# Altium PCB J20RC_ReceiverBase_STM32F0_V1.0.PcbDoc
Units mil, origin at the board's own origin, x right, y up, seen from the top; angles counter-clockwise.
Board outline 1700 x 955 mil, 2 copper layers (Top Layer, Bottom Layer); 27 components, 0 nets, 129 pads, 46 vias.
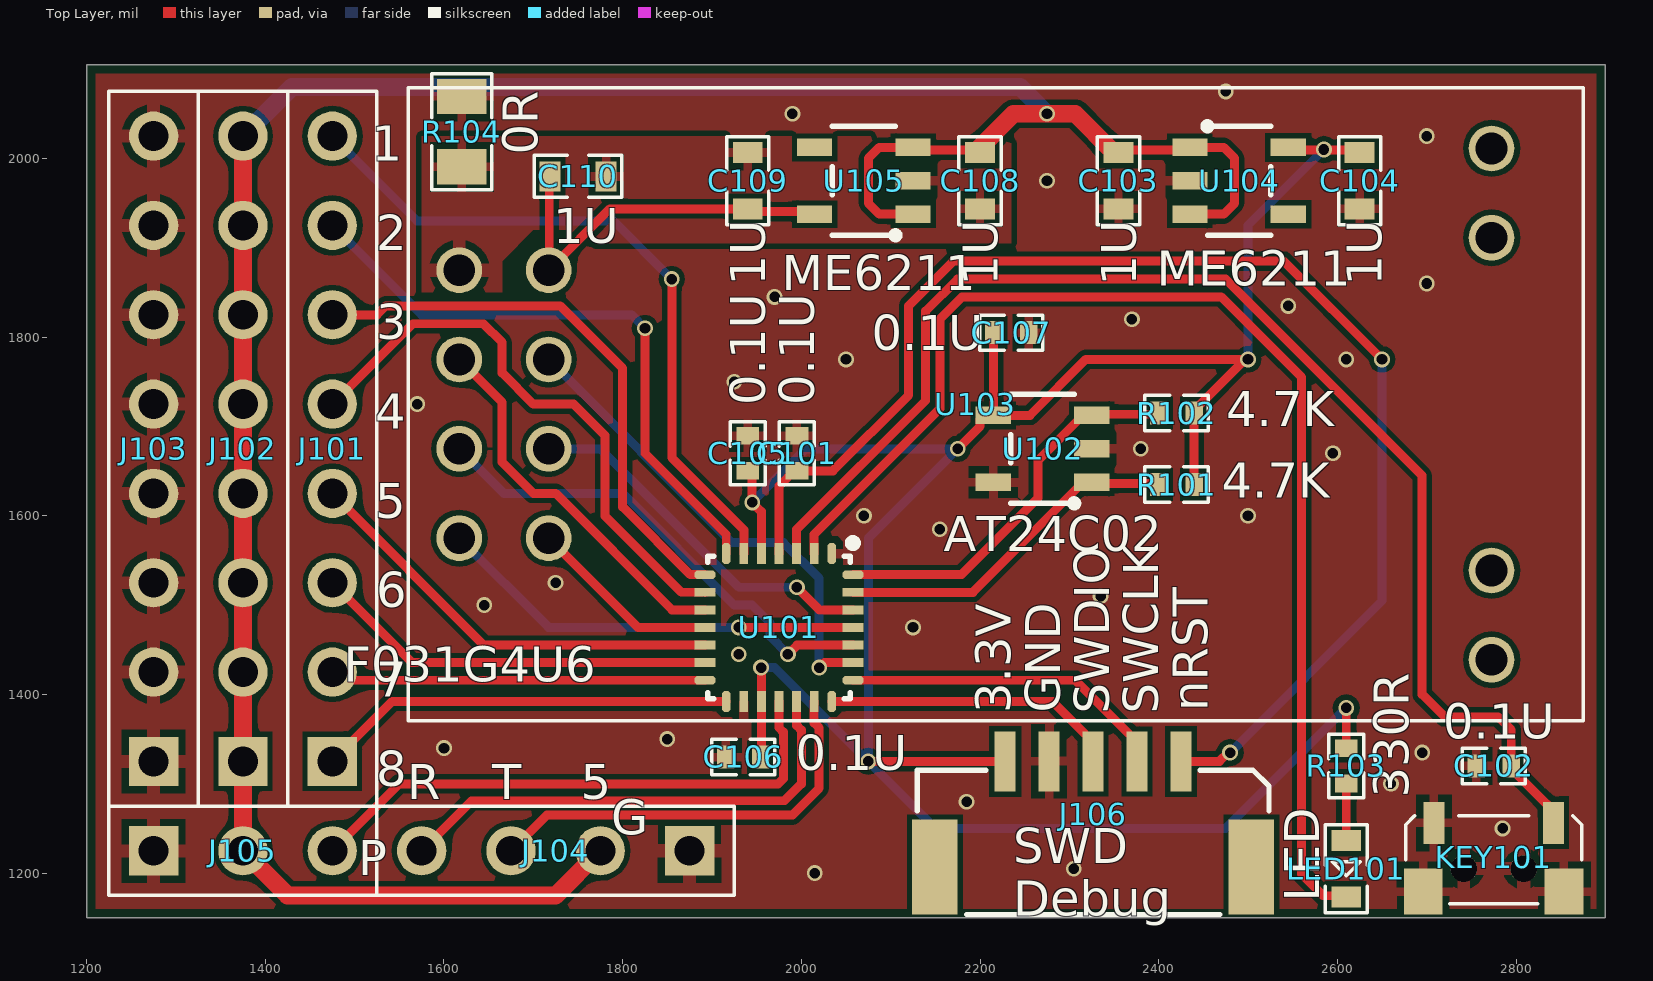
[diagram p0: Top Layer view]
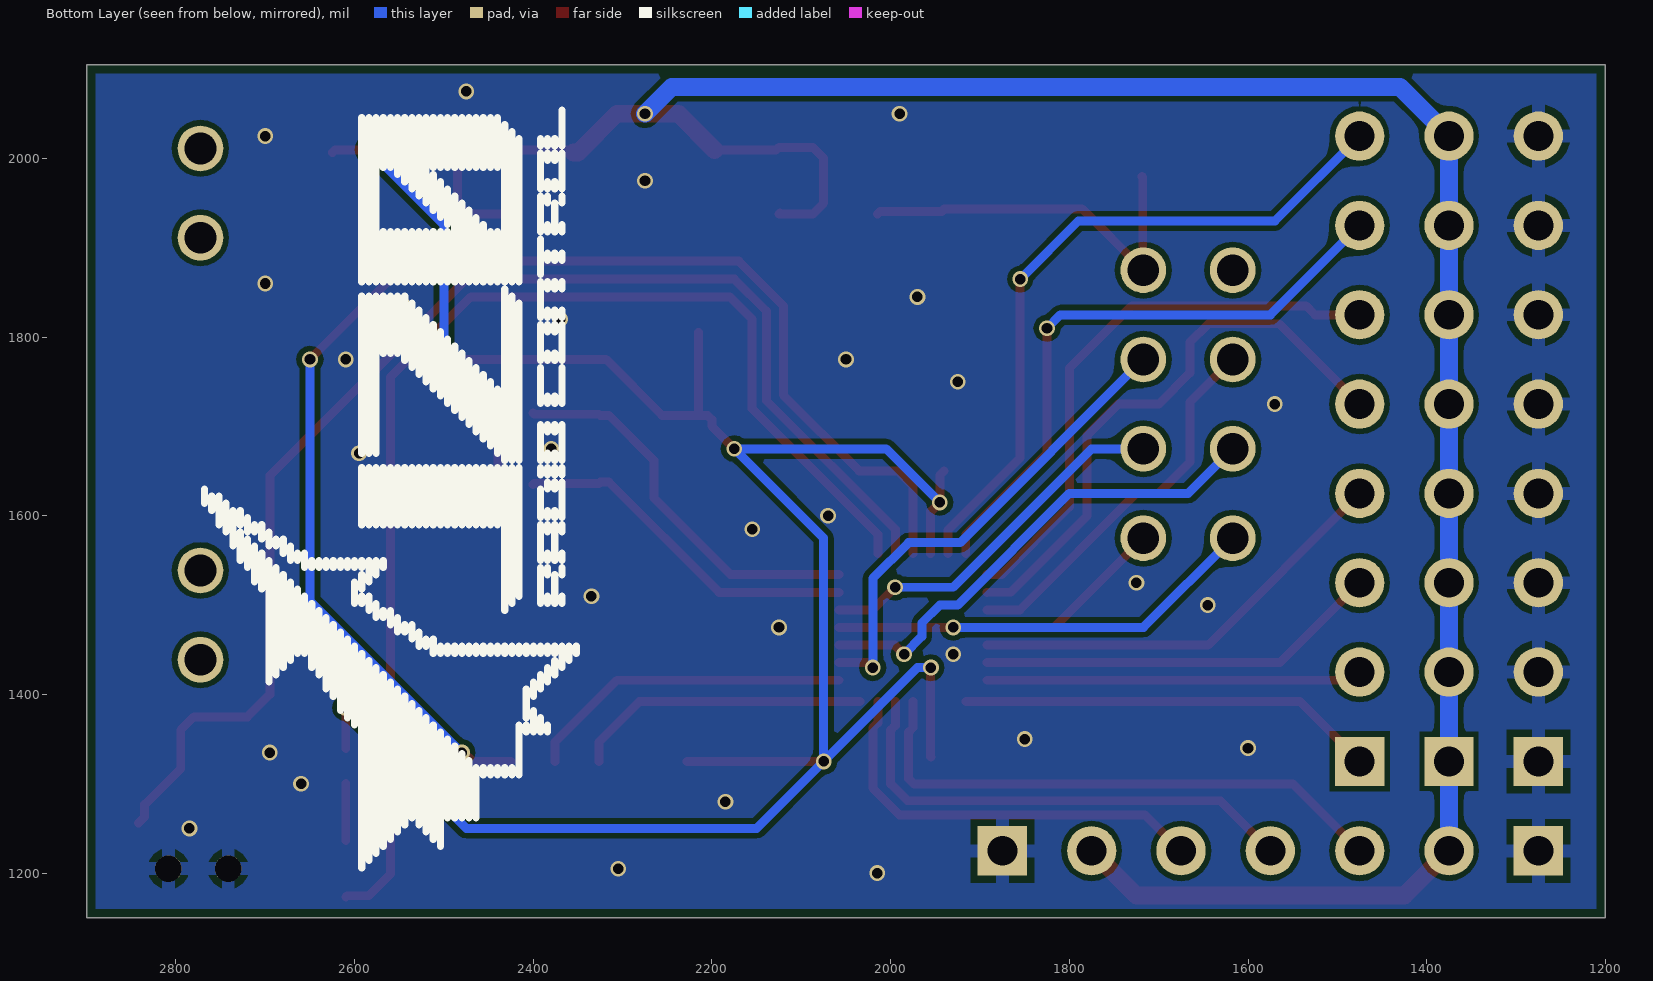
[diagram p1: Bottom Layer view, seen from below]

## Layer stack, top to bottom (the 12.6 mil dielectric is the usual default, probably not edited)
Top Solder: solder mask 0.4, Solder Resist, Dk 3.5
Top Layer: signal copper 1.4
Dielectric 1: dielectric 12.6, FR-4, Dk 4.8
Bottom Layer: signal copper 1.4
Bottom Solder: solder mask 0.4, Solder Resist, Dk 3.5

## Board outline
1200,1150 1200,2105 2900,2105 2900,1150

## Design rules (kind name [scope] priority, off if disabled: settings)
Clearance [All] p1: gap=10 ignorepadtopadclearanceinfootprint=FALSE except(0: Arc-Hole Track-Hole SMDPad-Hole THPad-Hole Via-Hole Fill-Hole Poly-Hole Region-Hole Text-Hole)
PolygonConnect [All] p1: connectstyle=Relief reliefconductorwidth=10 reliefentries=4 polygonreliefangle="90 Angle" airgapwidth=10
RoutingVias [All] p1: holewidth=28 width=50 viastyle="Through Hole" minholewidth=28 minwidth=50 maxholewidth=28 maxwidth=50
SolderMaskExpansion [All] p1: expansion=4
Width [All] p1: maxlimit=10 minlimit=10 preferedwidth=10
30 further rules are at their usual default settings.

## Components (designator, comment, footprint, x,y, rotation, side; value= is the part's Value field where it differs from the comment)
C101 "CAP" 0402 1995,1670 r90 top
C102 "CAP" 0402 2775,1320 r0 top
C103 "CAP" 0603 2355,1975 r90 top
C104 "CAP" 0603 2625,1975 r90 top
C105 "CAP" 0402 1940,1670 r270 top
C106 "CAP" 0402 1935,1330 r0 top
C107 "CAP" 0402 2235,1805 r180 top
C108 "CAP" 0603 2200,1975 r90 top
C109 "CAP" 0603 1940,1975 r270 top
C110 "CAP" 0603 1750,1980 r180 top
J101 "Header_8" Header_8_2.54 1475,1675 r90 top
J102 "Header_8" Header_8_2.54 1375,1675 r90 top
J103 "Header_8" Header_8_2.54 1275,1675 r90 top
J104 "Header_4" Header_4_2.54 1725,1225 r180 top
J105 "Header_3" Header_3_2.54 1375,1225 r0 top
J106 "IO5" GH1.25-5P 2425,1325 r270 top
KEY101 "KEY_2*4" KEY_2*4 2775,1205 r180 top
LED101 "LED" 0603_LED 2610,1205 r270 top
R101 "RES" 0402 2420,1635 r180 top
R102 "RES" 0402 2420,1715 r180 top
R103 "RES" 0402 2610,1320 r270 top
R104 "RES" 0805 1620,2030 r90 top
U101 "STM32F031G4U6" UFQFPN-28 1975,1475 r180 top
U102 "AT24C02D" SOT-23-5 2270,1675 r0 top
U103 "E01_2G4M27D" E01_2G4M27D 2875,1725 r90 top locked
U104 "ME6211" SOT-23-5 2490,1975 r180 top
U105 "ME6211" SOT-23-5 2070,1975 r0 top

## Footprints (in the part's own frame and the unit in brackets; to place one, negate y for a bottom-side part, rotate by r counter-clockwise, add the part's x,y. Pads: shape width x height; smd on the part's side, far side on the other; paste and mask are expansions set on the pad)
0402 [mm]
  rect 0.5x0.65 smd: 1(-0.5,0) 2(0.5,0)
  silkscreen extent -0.9,-0.5 0.9,0.5
0603 [mm]
  rect 0.6x0.85 smd: 1(-0.8,0) 2(0.8,0)
  silkscreen extent -1.25,-0.6 1.25,0.6
0603_LED [mm]
  rect 0.6x0.85 smd: 1(-0.8,0) 2(0.8,0)
  silkscreen extent -1.25,-0.6 1.25,0.6
0805 [mm]
  rect 1x1.4 smd: 1(-1,0) 2(1,0)
  silkscreen extent -1.65,-0.85 1.65,0.85
E01_2G4M27D [mm]
  round 1.3 hole 0.9: 1(3.81,31.95) 2(3.81,29.41) 3(1.27,31.95) 4(1.27,29.41) 5(-1.27,31.95) 6(-1.27,29.41) 7(-3.81,31.95) 8(-3.81,29.41) 9(7.27,2.6) 10(4.73,2.6) 11(-4.73,2.6) 12(-7.27,2.6)
  silkscreen extent -9,0 9,33.4
GH1.25-5P [mm]
  rect 1.7x0.6 smd: 1(0,0) 2(0,-1.25) 3(0,-2.5) 4(0,-3.75) 5(0,-5)
  rect 2.7x1.3 smd: 6(3,2) 7(3,-7)
  silkscreen extent 0.25,-7.5 4.35,2.5
Header_3_2.54 [mm]
  rect 1.4x1.4 hole 0.85: 1(-2.54,0)
  round 1.4 hole 0.85: 2(0,0) 3(2.54,0)
  silkscreen extent -3.81,-1.27 3.81,1.27
Header_4_2.54 [mm]
  rect 1.4x1.4 hole 0.85: 1(-3.81,0)
  round 1.4 hole 0.85: 2(-1.27,0) 3(1.27,0) 4(3.81,0)
  silkscreen extent -5.08,-1.27 5.08,1.27
Header_8_2.54 [mm]
  rect 1.4x1.4 hole 0.85: 1(-8.89,0)
  round 1.4 hole 0.85: 2(-6.35,0) 3(-3.81,0) 4(-1.27,0) 5(1.27,0) 6(3.81,0) 7(6.35,0) 8(8.89,0)
  silkscreen extent -10.16,-1.27 10.16,1.27
KEY_2*4 [mm]
  rect 0.6x1.2 smd: 1(-1.7,-1.3) 2(1.7,-1.3)
  rect 1.1x1.3 smd: 3(-2,0.65) 4(2,0.65)
  round 0.75 hole 0.75: 5(-0.85,0) 6(0.85,0)
  silkscreen extent -2.5,-1.5 2.5,1
SOT-23-5 [mm]
  rect 1x0.5 smd: 1(1.4,-0.95) 2(1.4,0) 3(1.4,0.95) 4(-1.4,0.95) 5(-1.4,-0.95)
  silkscreen extent -0.9,-1.68 1.03,1.55
UFQFPN-28 [mm]
  oct 0.25x0.6 smd: 1(-1.5,-2.1) 7(1.5,-2.1) 15(1.5,2.1) 21(-1.5,2.1)
  rect 0.25x0.6 smd: 2(-1,-2.1) 3(-0.5,-2.1) 4(0,-2.1) 5(0.5,-2.1) 6(1,-2.1) 16(1,2.1) 17(0.5,2.1) 18(0,2.1) 19(-0.5,2.1) 20(-1,2.1)
  oct 0.6x0.25 smd: 8(2.1,-1.5) 14(2.1,1.5) 22(-2.1,1.5) 28(-2.1,-1.5)
  rect 0.6x0.25 smd: 9(2.1,-1) 10(2.1,-0.5) 11(2.1,0) 12(2.1,0.5) 13(2.1,1) 23(-2.1,1) 24(-2.1,0.5) 25(-2.1,0) 26(-2.1,-0.5) 27(-2.1,-1)
  silkscreen extent -2.2,-2.5 2.02,2.02

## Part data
C101 C102 C103 C104 C105 C106 C107 C108 C109 C110: "无极性电容"
J101 J102 J103: "8P_排针"
J104: "4P_排针"
J105: "3P_排针"
R101 R102 R103 R104: "电阻"
U101: library part QFN28_ALL, "STM32F***G*U6"
U104 U105: "500mA LDO"

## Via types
v1: diameter 17.72, hole 11.81, Top Layer to Bottom Layer, tented both sides, 46 vias

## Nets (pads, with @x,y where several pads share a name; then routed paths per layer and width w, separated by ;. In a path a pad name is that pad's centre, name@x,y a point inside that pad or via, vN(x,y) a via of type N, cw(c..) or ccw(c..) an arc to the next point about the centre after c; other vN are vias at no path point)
pads on no net: C101.1 C101.2 C102.1 C102.2 C103.1 C103.2 C104.1 C104.2 C105.1 C105.2 C106.1 C106.2 C107.1 C107.2 C108.1 C108.2 C109.1 C109.2 C110.1 C110.2 J101.1 J101.2 J101.3 J101.4 J101.5 J101.6 J101.7 J101.8 J102.1 J102.2 J102.3 J102.4 J102.5 J102.6 J102.7 J102.8 J103.1 J103.2 J103.3 J103.4 J103.5 J103.6 J103.7 J103.8 J104.1 J104.2 J104.3 J104.4 J105.1 J105.2 J105.3 J106.1 J106.2 J106.3 J106.4 J106.5 J106.6 J106.7 KEY101.1 KEY101.2 KEY101.3 KEY101.4 KEY101.5 KEY101.6 LED101.1 LED101.2 R101.1 R101.2 R102.1 R102.2 R103.1 R103.2 R104.1 R104.2 U101.1 U101.2 U101.3 U101.4 U101.5 U101.6 U101.7 U101.8 U101.9 U101.10 U101.11 U101.12 U101.13 U101.14 U101.15 U101.16 U101.17 U101.18 U101.19 U101.20 U101.21 U101.22 U101.23 U101.24 U101.25 U101.26 U101.27 U101.28 U102.1 U102.2 U102.3 U102.4 U102.5 U103.1 U103.2 U103.3 U103.4 U103.5 U103.6 U103.7 U103.8 U103.9 U103.10 U103.11 U103.12 U104.1 U104.2 U104.3 U104.4 U104.5 U105.1 U105.2 U105.3 U105.4 U105.5
copper on no net: | length 21773
  Top Layer w10: 1475,1225 1550,1300 1974.14,1300 1980,1305.86 1980,1357.8 1975,1362.8 1975,1392.32 ; 1475,1325 1542.32,1392.32 1915.94,1392.32 ; 1475,1425 1487.21,1425 1496.26,1415.94 1892.32,1415.94 ; 1475,1525 1564.37,1435.63 1892.32,1435.63 ; 1475,1625 1644.69,1455.31 1892.32,1455.31 ; 1475,1725 1565,1815 1644.14,1815 1665,1794.14 1665,1760 1700,1725 1745,1725 1780,1690 1780,1600 1865.55,1514.45 1892.24,1514.45 1892.32,1514.37 ; 1475,1825 1525,1825 1535,1835 1730,1835 1800,1765 1800,1610 1875.87,1534.13 1892.24,1534.13 1892.32,1534.06 ; 1575,1225 1631,1281 1981,1281 2000,1300 2000,1360 1994.68,1365.32 1994.68,1392.32 ; 1617.13,1775 1665,1727.13 1665,1660 1700,1625 1725,1625 1855.24,1494.76 1892.24,1494.76 1892.32,1494.68 ; 1675,1225 1715,1265 1990,1265 2020,1295 2020,1362.63 2014.37,1368.26 2014.37,1392.32 ; 1717.13,1575 1817.13,1475 1892.32,1475 ; 1717.13,1875 1717.81,1875.69 ; 1718.5,1980 1717.81,1979.31 1717.81,1875.69 ; v1(1825,1810) 1825,1670 1915.94,1579.06 1915.94,1557.68 ; v1(1855,1865) 1855,1665 1935.63,1584.37 1935.63,1557.68 ; v1(1930,1475) 2057.68,1475 ; 1940,1650.32 1940.16,1650.32 1945,1645.48 v1(1945,1615) 1955.32,1604.68 1955.32,1557.68 ; 1954.68,1330 1955.23,1330.55 1955.23,1392.24 1955.31,1392.32 1955.23,1392.4 1955.23,1429.77 v1(1955,1430) ; 1975,1557.68 1975,1633.26 1992.05,1650.32 1995,1650.32 2035.32,1650.32 2120,1735 2120,1835 2170,1885 2540,1885 v1(2650,1775) ; v1(1985,1445) 1995.32,1455.32 2057.68,1455.32 ; 1994.68,1557.68 1994.68,1584.68 2139,1729 2139,1829 2175,1865 2475,1865 2695,1645 2695,1400 2720,1375 2780,1375 2794.68,1360.32 2794.68,1320 2794.68,1317.04 2835.12,1276.61 2835.12,1262.99 2841.93,1256.18 ; v1(1995,1520) 2020.32,1494.68 2057.68,1494.68 ; 2014.37,1557.68 2014.37,1579.37 2155,1720 2155,1820 2180,1845 2470,1845 2560,1755 2560,1198.84 2584.13,1174.71 2608.79,1174.71 2610,1173.5 ; 2014.88,1937.6 2011.93,1940.55 1942.95,1940.55 1940,1943.5 1785.63,1943.5 1717.81,1875.69 ; v1(2020,1430) 2025.63,1435.63 2057.68,1435.63 ; 2034.06,1392.32 2280.93,1392.32 2326.58,1346.67 2326.58,1325 ; 2057.68,1415.94 2306.51,1415.94 2375.78,1346.68 2375.78,1325.01 ; 2057.68,1514.37 2192.05,1514.37 2315.28,1637.6 2325.12,1637.6 2326.42,1636.3 2399.02,1636.3 2400.31,1635 ; 2057.68,1534.06 2179.06,1534.06 2265,1620 2265,1662.13 2315.28,1712.4 2325.12,1712.4 2326.42,1713.7 2399.02,1713.7 2400.32,1715 ; v1(2075,1325) 2228.15,1325.01 ; 2124.01,1938.71 2125.12,1937.6 2087.4,1937.6 2075,1950 2075,2000 2087.4,2012.4 2125.12,2012.4 2128.07,2009.45 2197.05,2009.45 ; v1(2175,1675) 2200.2,1700.2 2200.2,1707.56 2205.04,1712.4 2214.88,1712.4 ; 2215.32,1804.99 2215.32,1712.84 2214.88,1712.4 ; 2355,2006.5 2357.95,2009.45 2431.93,2009.45 2434.88,2012.4 2472.6,2012.4 2485,2000 2485,1950 2472.6,1937.6 2434.88,1937.6 ; 2425,1325.01 2467.92,1325.01 2477.91,1335 v1(2480,1335) ; 2439.69,1635.01 2439.69,1714.99 2439.68,1717.95 v1@2496.74,1775 ; v1(2500,1775) v1@2496.74,1775 ; 2545.12,2012.4 2548.07,2009.45 2622.05,2009.45 2625,2006.5 ; 2610,1236.5 2610,1300.31 ; 2610,1339.68 v1(2610,1385) ; 2214.88,1712.4 2255.98,1712.4 2318.58,1775 v1@2496.74,1775
  Top Layer w20: 1375,2025 1375,1925 1375,1825 1375,1725 1375,1625 1375,1525 1375,1425 1375,1325 1375,1225 1425,1175 1725,1175 1775,1225 ; 2197.05,2009.45 2237.59,2050 v1(2275,2050) 2306.58,2050 2350.08,2006.5 2355,2006.5
  Bottom Layer w10: 1475,1925 1575,1825 1810,1825 v1(1825,1810) ; 1475,2025 1570,1930 1790,1930 v1(1855,1865) ; 1617.13,1575 1717.13,1475 v1(1930,1475) ; 1617.13,1675 1667.13,1625 1800,1625 1925,1500 1945,1500 1965,1480 1965,1465 v1(1985,1445) ; 1717.13,1675 1775,1675 1930,1520 v1(1995,1520) ; 1717.13,1775 1922.13,1570 1980,1570 2020,1530 v1(2020,1430) ; v1(1945,1615) 2005,1675 v1(2175,1675) 2075,1575 v1(2075,1325) ; v1(1955,1430) 1970,1430 v1(2075,1325) ; v1(2480,1335) 2650,1505 v1(2650,1775) ; v1(2500,1775) 2500,1925 v1(2585,2010) ; v1(2610,1385) 2475,1250 2150,1250 v1(2075,1325)
  Bottom Layer w20: 1375,1225 1375,1325 1375,1425 1375,1525 1375,1625 1375,1725 1375,1825 1375,1925 1375,2025 1430,2080 2245,2080 v1(2275,2050)
  other v1: 2015,1200 2305,1205 2785,1250 2185,1280 2660,1300 2695,1335 1600,1340 1850,1350 1930,1445 2125,1475 1645,1500 2335,1510 1725,1525 2155,1585 2070,1600 2500,1600 2595,1670 2380,1675 1570,1725 1925,1750 2050,1775 2610,1775 2370,1820 2545,1835 1970,1845 2700,1860 2275,1975 2700,2025 1990,2050 2475,2075

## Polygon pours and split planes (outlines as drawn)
no net on Top Layer "NONET_L01_P001" (solid, pour order 1): 1210,1160 1210.35,1160.35 2889.83,1160.35 2889.83,2094.83 2890,2095 1210,2095
no net on Top Layer "NONET_L01_P000" (solid, pour order 0): 1575,2025 2235,2025 2235,1905 1755,1905 1740,1920 1700,1920 1665,1885 1665,1850 1575,1850
no net on Bottom Layer "NONET_L02_P002" (solid, pour order 2): 1210,2095 2890,2095 2890,1160 1210,1160

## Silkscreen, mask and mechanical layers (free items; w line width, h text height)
Top Overlay:
  text "0R" at 1704.68,2004.35 h39.37 r90
  text "1" at 1519.01,1997.45 h39.37
  text "1U" at 1722.45,1905.32 h39.37
  text "2" at 1524.01,1897.45 h39.37
  text "1U" at 1959.68,1857.45 h39.37 r90
  text "1U" at 2219.68,1857.45 h39.37 r90
  text "1U" at 2374.68,1857.45 h39.37 r90
  text "ME6211" at 2397.91,1857.45 h39.37
  text "1U" at 2649.68,1857.45 h39.37 r90
  text "ME6211" at 1977.91,1852.45 h39.37
  text "3" at 1524.01,1797.45 h39.37
  text "0.1U" at 2078.74,1785.32 h39.37
  text "0.1U" at 1959.68,1723.74 h39.37 r90
  text "0.1U" at 2014.68,1723.74 h39.37 r90
  text "4.7K" at 2475.64,1700.32 h39.37
  text "4" at 1523.07,1697.45 h39.37
  text "4.7K" at 2470.64,1620.32 h39.37
  text "5" at 1523.07,1597.45 h39.37
  text "AT24C02" at 2159.67,1560.32 h39.37
  text "6" at 1524.01,1497.45 h39.37
  text "F031G4U6" at 1487.73,1414.38 h39.37
  text "7" at 1524.01,1397.45 h39.37
  text "nRST" at 2454.68,1381.37 h39.37 r90
  text "GND" at 2289.68,1379.77 h39.37 r90
  text "3.3V" at 2234.68,1378.77 h39.37 r90
  text "SWCLK" at 2399.68,1378.69 h39.37 r90
  text "SWDIO" at 2344.68,1378.15 h39.37 r90
  text "0.1U" at 2718.74,1350.32 h39.37
  text "0.1U" at 1993.74,1315.32 h39.37
  text "8" at 1524.01,1297.45 h39.37
  text "330R" at 2679.68,1284.3 h39.37 r90
  text "R" at 1559.01,1282.45 h39.37
  text "T" at 1654.01,1282.45 h39.37
  text "5" at 1753.07,1282.45 h39.37
  text "G" at 1786.96,1242.82 h39.37
  text "P" at 1504.01,1197.45 h39.37
  text "LED" at 2579.68,1168.01 h39.37 r90
  text "SWD / Debug" at 2236.96,1152.16 h39.37
Bottom Overlay:
  drawing of 262 lines, arcs and shapes, not listed
Mechanical 1:
  lines w3.94: 1200,2105 1200,1150 2900,1150 2900,2105 1200.71,2105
